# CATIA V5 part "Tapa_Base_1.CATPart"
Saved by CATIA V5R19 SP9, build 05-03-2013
Part number: Tapa_Base_1
Bounding box of the stored display mesh (mm): x -100 to 100, y -1.5 to 155, z -2.4 to 3
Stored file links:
  D:\PROGRAMACION\PROYECTOS\DEFCON\CAD\Tapa_Base_1.CATPart
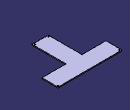
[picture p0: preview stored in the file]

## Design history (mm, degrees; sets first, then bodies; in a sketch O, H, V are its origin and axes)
Set1
  DatumCurve1 to DatumCurve21
  DatumSurface1
  DatumSurface2
  DatumCurve22 to DatumCurve29
Body1 (main body)
  Sketch1 on xy-plane, origin (0, 0, 0), H (1, 0, 0), V (0, 1, 0)
    point P1 (-25, 0)
    line L1 (-25, 0) -> (25, 0)
    line L2 (25, 0) -> (25, 105)
    line L3 (25, 105) -> (100, 105)
    line L4 (100, 105) -> (100, 155)
    line L5 (100, 155) -> (-100, 155)
    line L6 (-100, 155) -> (-100, 105)
    point P7 (-100, 105)
    line L7 (-100, 105) -> (-25, 105)
    line L8 (-25, 105) -> (-25, 0)
    length L1 = 50
    length L7 = 75
    length L2 = 105
    length L4 = 50
    coincidence: P1 H, P7 L3
    horizontal: L1 H, L3 H, L5 H, L7 H
    vertical: L2 V, L4 V, L6 V, L8 V
    symmetry: L8 L2 V, L6 L4 V
  Pad1: profile Sketch1, direction (0, 0, 1), length 3
  Sketch2 on end face of Pad1, origin (0, 0, 3), H (1, 0, 0), V (0, 1, 0)
    reference projected circle E1 centre (-96, 151) radius 2.5 from edge of DatumCurve1
    reference projected circle E3 centre (-21, 4) radius 2.5 from edge of DatumCurve3
    axis line L1 (0, 174.0259) -> (0, -25.0037)
    reference projected line E5 (-25, 105) -> (-25, 0) from edge [start face of Pad1 | face of Pad1 from Sketch1.L8]
    reference projected line E6 (25, 0) -> (25, 105) from edge [start face of Pad1 | face of Pad1 from Sketch1.L2]
    circle A1 centre (-96, 151) radius 1.7
    circle A2 centre (-21, 4) radius 1.7
    circle A3 centre (96, 151) radius 1.7
    circle A4 centre (21, 4) radius 1.7
    radius A1 = 1.7
    radius A2 = 1.7
    coincidence: L1 O
    symmetry: E5 E6 L1, A1 A3 L1, A2 A4 L1
    concentricity: A1 E1, A2 E3
  Pocket1: profile Sketch2, direction (0, 0, -1), through (limit type 6)
  Sketch3 on zx-plane, origin (0, 0, 0), H (-1, 0, 0), V (0, 0, 1)
    projected line E1 (25, 0) -> (-25, 0) from edge [start face of Pad1 | face of Pad1 from Sketch1.L1]
    projected line E2 (2.4, 0) -> (1.6, 0) from edge [start face of Pad1 | face of Pad1 from Sketch1.L1]
    projected line E3 (-1.6, 0) -> (-2.4, 0) from edge [start face of Pad1 | face of Pad1 from Sketch1.L1]
    arc A1 centre (0, 0) radius 2.4 from (-2.4, 0) to (2.4, 0) ccw
    arc A2 centre (0, 0) radius 1.6 from (-1.6, 0) to (1.6, 0) ccw
    point P3 (-2.4, 0)
    point P4 (2.4, 0)
    point P5 (-1.6, 0)
    point P6 (1.6, 0)
    radius A1 = 2.4
    radius A2 = 1.6
    coincidence: E1 P4, E1 P3, E1 P6, E1 P5
  Pad2: profile Sketch3, direction (0, 1, 0), up to face of DatumSurface1, opposite side up to face of Pad4 from Sketch6.L2
  Body2
    Sketch4 on start face of Pad1, origin (0, 0, 0), H (1, 0, 0), V (0, -1, 0)
      reference projected line E1 (23, -3) -> (-23, -3) from edge of DatumCurve5
      reference projected line E4 (-23, -49) -> (23, -49) from edge of DatumCurve8
      reference projected line E5 (23, -55) -> (-23, -55) from edge of DatumCurve9
      reference projected line E9 (98, -107) -> (-98, -107) from edge of DatumCurve13
      reference projected line E11 (-98, -153) -> (98, -153) from edge of DatumCurve15
      line L1 (-21, -3) -> (21, -3)
      line L2 (21, -3) -> (21, -49)
      line L3 (21, -49) -> (-21, -49)
      line L4 (-21, -49) -> (-21, -3)
      point P29 (-21, -55)
      line L5 (-21, -55) -> (21, -55)
      line L6 (21, -55) -> (21, -101)
      line L7 (21, -101) -> (-21, -101)
      line L8 (-21, -101) -> (-21, -55)
      point P31 (21, -101)
      construction line L9 (0, 41) -> (0, -173)
      point P33 (0, 41)
      construction line L10 (-40, -52) -> (61, -52)
      construction line L11 (-90, -113.5) -> (90, -113.5)
      construction line L12 (90, -113.5) -> (90, -146.5)
      construction line L13 (90, -146.5) -> (-90, -146.5)
      construction line L14 (-90, -146.5) -> (-90, -113.5)
      axis line L15 (-115, -130) -> (134, -130)
      length L2 = 46
      length L3 = 42
      length L6 = 46
      distance L3 E4 = 0
      distance E1 L1 = 0 (reference)
      length L13 = 180
      length L12 = 33
      horizontal: L1 H, L3 H, L5 H, L7 H, L10 H, L11 H, L13 H, L15 H
      vertical: L2 V, L4 V, L6 V, L8 V, L9 V, L12 V, L14 V
      coincidence: P29 L4, P31 L2, P33 V
      symmetry: L4 L2 L9, E4 E5 L10, L3 L5 L10, E9 E11 L15, L11 L13 L15, L14 L12 L9
    Pocket2: profile Sketch4, direction (0, 0, 1), up to face of DatumSurface2
  Remove1: tool Body2
  Body3
    Sketch5 on face of Pad1 from Sketch1.L6, origin (-100, 0, 0), H (0, -1, 0), V (0, 0, 1)
      arc A1 centre (-115, 0) radius 2.4 from (-117.4, 0) to (-112.6, 0) ccw
      point P1 (-115, 0)
      arc A2 centre (-115, 0) radius 1.6 from (-116.6, 0) to (-113.4, 0) ccw
      projected line E1 (-155, 0) -> (-105, 0) from edge [face of Pad1 | face of Pad1 from Sketch1.L6]
      projected line E2 (-117.4, 0) -> (-116.6, 0) from edge [face of Pad1 | face of Pad1 from Sketch1.L6]
      projected line E3 (-113.4, 0) -> (-112.6, 0) from edge [face of Pad1 | face of Pad1 from Sketch1.L6]
      reference projected line E4 (-105, 0) -> (-105, 3) from edge [face of Pad1 from Sketch1.L7 | face of Pad1 from Sketch1.L6]
      point P4 (-117.4, 0)
      point P5 (-112.6, 0)
      point P6 (-116.6, 0)
      point P7 (-113.4, 0)
      point P8 (-116.6, 0)
      point P9 (-113.4, 0)
      point P10 (-117.4, 0)
      point P11 (-112.6, 0)
      radius A2 = 1.6
      radius A1 = 2.4
      distance P1 E4 = 10
      coincidence: P1 E1, A1 P4, A1 P5, A2 P6, A2 P7, E1 P9, E1 P8, E1 P11, E1 P10, P4 P10, P5 P11, P6 P8, P7 P9
    Pad3: profile Sketch5, direction (1, 0, 0), length 80, opposite side length -20, deactivated
  Add1: tool Body3, deactivated
  Body4
    Sketch6 on end face of Pad1, origin (0, 0, 3), H (1, 0, 0), V (0, 1, 0)
      axis line L1 (0, 22) -> (0, -20)
      point P1 (0, 22)
      point P3 (25, 0)
      point P4 (0, -1.5)
      line L2 (0, -1.5) -> (4.4641, -1.5)
      point P5 (4.4641, -1.5)
      line L3 (4.4641, -1.5) -> (3.5981, 0)
      point P6 (3.5981, 0)
      point P7 (9.5981, 0)
      line L4 (9.5981, 0) -> (8.7321, -1.5)
      point P8 (8.7321, -1.5)
      line L5 (8.7321, -1.5) -> (14.7321, -1.5)
      point P9 (14.7321, -1.5)
      line L6 (14.7321, -1.5) -> (13.866, 0)
      point P10 (13.866, 0)
      point P11 (19.866, 0)
      line L7 (19.866, 0) -> (19, -1.5)
      point P12 (19, -1.5)
      line L8 (19, -1.5) -> (25, -1.5)
      point P13 (25, -1.5)
      reference projected point E1 (25, 0) from vertex [face of Pad1 from Sketch1.L2 | end face of Pad1 | face of Pad1 from Sketch1.L1]
      construction line L9 through (0, 0) direction (-1, 0)
      point P14 (0, -1.5)
      line L10 (25, -1.5) -> (25, 0)
      point P15 (25, 0)
      line L11 (25, 0) -> (19.866, 0)
      line L12 (13.866, 0) -> (9.5981, 0)
      line L13 (3.5981, 0) -> (0, 0)
      point P16 (0, 0)
      reference projected point E2 (25, 0) from vertex [face of Pad1 from Sketch1.L2 | end face of Pad1 | face of Pad1 from Sketch1.L1]
      point P17 (0, 0)
      construction line L14 through (0, 0) direction (-1, 0)
      construction line L15 through (0, 0) direction (0, 1)
      point P18 (-25, 0)
      point P19 (0, -1.5)
      point P20 (-4.4641, -1.5)
      point P21 (-3.5981, 0)
      point P22 (-9.5981, 0)
      point P23 (-8.7321, -1.5)
      point P24 (-14.7321, -1.5)
      point P25 (-13.866, 0)
      point P26 (-19.866, 0)
      point P27 (-19, -1.5)
      point P28 (-25, -1.5)
      point P29 (0, -1.5)
      point P30 (-25, 0)
      point P31 (0, 0)
      line L16 (0, -1.5) -> (-4.4641, -1.5)
      line L17 (-4.4641, -1.5) -> (-3.5981, 0)
      line L18 (-9.5981, 0) -> (-8.7321, -1.5)
      line L19 (-8.7321, -1.5) -> (-14.7321, -1.5)
      line L20 (-14.7321, -1.5) -> (-13.866, 0)
      line L21 (-19.866, 0) -> (-19, -1.5)
      line L22 (-19, -1.5) -> (-25, -1.5)
      line L23 (-25, -1.5) -> (-25, 0)
      line L24 (-25, 0) -> (-19.866, 0)
      line L25 (-13.866, 0) -> (-9.5981, 0)
      line L26 (-3.5981, 0) -> (0, 0)
      length L8 = 6
      length L5 = 6 {= Sketch6.length(L8)}
      angle L4 L5 = 60
      angle L3 L2 = 60
      angle L8 L7 = 60
      angle L6 L5 = 60
      distance P10 P11 = 6 {= Sketch6.length(L8)}
      distance P6 P7 = 6 {= Sketch6.length(L8)}
      length L10 = 1.5
      coincidence: P1 V, P3 H, P8 L2, P12 L5, P3 E1, P14 P4, P16 L1, L11 L9, L12 L9, L10 E2, L13 L9, P4 P19, P16 P31
      vertical: L1 V, L10 V
      horizontal: L2 H, L5 H, L8 H, L11 H, L12 H, L13 H
      symmetry: H L9 L1, P4 P14 L1, O P17 L1, H L14 L1, V L15 L1, P3 P18 L1, P4 P19 L1, P5 P20 L1, P6 P21 L1, P7 P22 L1, P8 P23 L1, P9 P24 L1, P10 P25 L1, P11 P26 L1, P12 P27 L1, P13 P28 L1, P14 P29 L1, P15 P30 L1, P16 P31 L1, L2 L16 L1, L3 L17 L1, L4 L18 L1, L5 L19 L1, L6 L20 L1, L7 L21 L1, L8 L22 L1, L10 L23 L1, L11 L24 L1, L12 L25 L1, L13 L26 L1
    Pad4: profile Sketch6, direction (0, 0, 1), up to face of Pad1
  Add2: tool Body4
  Fillet1: radius 0.3, on edge [face of Pad4 from Sketch6.L7 | face of Pad4 from Sketch6.L8]; edge [face of Pad1 from Sketch1.L1 | face of Pad4 from Sketch6.L7]; edge [face of Pad4 from Sketch6.L6 | face of Pad1 from Sketch1.L1]; edge [face of Pad4 from Sketch6.L5 | face of Pad4 from Sketch6.L6]; edge [face of Pad1 from Sketch1.L1 | face of Pad4 from Sketch6.L4]; edge [face of Pad4 from Sketch6.L4 | face of Pad4 from Sketch6.L5]; edge [face of Pad4 from Sketch6.L3 | face of Pad1 from Sketch1.L1]; edge [face of Pad2 | face of Pad4 from Sketch6.L3]; edge [face of Pad4 from Sketch6.L17 | face of Pad2]; edge [face of Pad1 from Sketch1.L1 | face of Pad4 from Sketch6.L17]; edge [face of Pad4 from Sketch6.L18 | face of Pad1 from Sketch1.L1]; edge [face of Pad4 from Sketch6.L19 | face of Pad4 from Sketch6.L18]; edge [face of Pad4 from Sketch6.L20 | face of Pad4 from Sketch6.L19]; edge [face of Pad1 from Sketch1.L1 | face of Pad4 from Sketch6.L20]; edge [face of Pad4 from Sketch6.L21 | face of Pad1 from Sketch1.L1]; edge [face of Pad4 from Sketch6.L22 | face of Pad4 from Sketch6.L21]
  Sketch7 on start face of Pad1, origin (0, 0, 0), H (1, 0, 0), V (0, -1, 0)
Body5
  Sketch8 on face of Pad1, origin (0, 0, 0), H (1, 0, 0), V (0, -1, 0)
    projected line E1 (-23, -3) -> (-23, -49) from edge of DatumCurve22
    point P1 (-23, -3)
    point P2 (-23, -49)
    projected line E2 (23, -3) -> (-23, -3) from edge of DatumCurve23
    point P3 (23, -3)
    point P4 (-23, -3)
    projected line E3 (23, -49) -> (23, -3) from edge of DatumCurve24
    point P5 (23, -49)
    point P6 (23, -3)
    projected line E4 (-23, -49) -> (23, -49) from edge of DatumCurve25
    point P7 (-23, -49)
    point P8 (23, -49)
    projected line E5 (23, -55) -> (-23, -55) from edge of DatumCurve26
    projected line E6 (-23, -55) -> (-23, -101) from edge of DatumCurve27
    projected line E7 (23, -101) -> (23, -55) from edge of DatumCurve28
    projected line E8 (-23, -101) -> (23, -101) from edge of DatumCurve29
    construction line L1 (0, 40) -> (0, -129)
    point P17 (0, 40)
    construction line L2 (-66, -52) -> (63, -52)
    axis line L3 (-62, -26) -> (72, -26)
    point P23 (-22.8, -11)
    line L4 (-22.8, -11) -> (-22, -11)
    line L5 (-22, -11) -> (-22, -41)
    line L6 (-22, -41) -> (-22.8, -41)
    line L7 (-22.8, -41) -> (-22.8, -11)
    point P24 (-22, -11)
    point P25 (-22, -41)
    point P26 (-22.8, -41)
    point P27 (-15, -3.2)
    line L8 (-15, -3.2) -> (-4, -3.2)
    line L9 (15, -3.2) -> (15, -4)
    line L10 (15, -4) -> (4, -4)
    line L11 (-15, -4) -> (-15, -3.2)
    point P28 (15, -3.2)
    point P29 (15, -4)
    point P30 (-15, -4)
    point P31 (15, -48.8)
    point P32 (-15, -48.8)
    point P33 (-15, -48)
    point P34 (15, -48)
    point P35 (22, -11)
    point P36 (22.8, -11)
    line L12 (22.8, -11) -> (22, -11)
    point P37 (22.8, -41)
    line L13 (22.8, -41) -> (22.8, -11)
    point P38 (22, -41)
    line L14 (22, -11) -> (22, -41)
    line L15 (22, -41) -> (22.8, -41)
    point P39 (0, -104)
    construction line L16 through (0, -104) direction (1, 0)
    construction line L17 through (0, -104) direction (0, -1)
    point P40 (-23, -55)
    point P41 (-23, -101)
    point P42 (-23, -101)
    point P43 (23, -101)
    point P44 (23, -101)
    point P45 (23, -55)
    point P46 (23, -55)
    point P47 (-23, -55)
    point P48 (-22.8, -93)
    point P49 (-22, -93)
    point P50 (-22, -63)
    point P51 (-22.8, -63)
    point P52 (22, -93)
    point P53 (22.8, -93)
    point P54 (22.8, -63)
    point P55 (22, -63)
    line L18 (-22.8, -93) -> (-22, -93)
    line L19 (-22, -93) -> (-22, -63)
    line L20 (-22, -63) -> (-22.8, -63)
    line L21 (-22.8, -63) -> (-22.8, -93)
    line L22 (22.8, -93) -> (22, -93)
    line L23 (22.8, -63) -> (22.8, -93)
    line L24 (22, -93) -> (22, -63)
    line L25 (22, -63) -> (22.8, -63)
    construction line L26 (-23, -101) -> (-23, -55)
    construction line L27 (23, -101) -> (-23, -101)
    construction line L28 (23, -55) -> (23, -101)
    construction line L29 (-23, -55) -> (23, -55)
    line L30 (-4, -3.2) -> (-4, -4)
    point P56 (-4, -3.2)
    point P57 (-4, -4)
    line L31 (4, -3.2) -> (4, -4)
    point P58 (4, -3.2)
    point P59 (4, -4)
    line L32 (4, -3.2) -> (15, -3.2)
    line L33 (-4, -4) -> (-15, -4)
    point P60 (-15, -48.8)
    point P61 (-15, -48)
    line L34 (-15, -48) -> (-15, -48.8)
    point P62 (-4, -48.8)
    line L35 (-15, -48.8) -> (-4, -48.8)
    point P63 (-4, -48)
    line L36 (-4, -48) -> (-15, -48)
    line L37 (-4, -48.8) -> (-4, -48)
    point P64 (4, -48)
    point P65 (4, -48.8)
    line L38 (4, -48.8) -> (4, -48)
    point P66 (15, -48.8)
    line L39 (4, -48.8) -> (15, -48.8)
    point P67 (15, -48)
    line L40 (15, -48) -> (4, -48)
    line L41 (15, -48.8) -> (15, -48)
    point P68 (0, -104)
    construction line L42 through (0, -104) direction (1, 0)
    point P69 (-15, -100.8)
    point P70 (15, -100.8)
    point P71 (15, -100)
    point P72 (-15, -100)
    point P73 (15, -55.2)
    point P74 (-15, -55.2)
    point P75 (-15, -56)
    point P76 (15, -56)
    point P77 (-4, -100.8)
    point P78 (-4, -100)
    point P79 (4, -100.8)
    point P80 (4, -100)
    point P81 (-15, -55.2)
    point P82 (-15, -56)
    point P83 (-4, -55.2)
    point P84 (-4, -56)
    point P85 (4, -56)
    point P86 (4, -55.2)
    point P87 (15, -55.2)
    point P88 (15, -56)
    line L43 (-15, -100.8) -> (-4, -100.8)
    line L44 (15, -100.8) -> (15, -100)
    line L45 (15, -100) -> (4, -100)
    line L46 (-15, -100) -> (-15, -100.8)
    line L47 (-4, -100.8) -> (-4, -100)
    line L48 (4, -100.8) -> (4, -100)
    line L49 (4, -100.8) -> (15, -100.8)
    line L50 (-4, -100) -> (-15, -100)
    line L51 (-15, -56) -> (-15, -55.2)
    line L52 (-15, -55.2) -> (-4, -55.2)
    line L53 (-4, -56) -> (-15, -56)
    line L54 (-4, -55.2) -> (-4, -56)
    line L55 (4, -55.2) -> (4, -56)
    line L56 (4, -55.2) -> (15, -55.2)
    line L57 (15, -56) -> (4, -56)
    line L58 (15, -55.2) -> (15, -56)
    length L5 = 30
    distance L7 E1 = 0.2
    length L6 = 0.8
    distance L8 E2 = 0.2
    length L9 = 0.8
    distance P29 P30 = 30
    distance L30 L31 = 8
    length L33 = 11 (reference)
    coincidence: P17 V, P57 L10, P58 L8, L8 L32, L10 L33
    vertical: L1 V, L5 V, L7 V, L9 V, L11 V, L30 V, L31 V
    horizontal: L2 H, L3 H, L4 H, L6 H, L8 H, L10 H, L32 H, L33 H
    symmetry: E4 E5 L2, E1 E3 L1, E2 E4 L3, L4 L6 L3, L11 L9 L1, P28 P31 L3, P27 P32 L3, P30 P33 L3, P29 P34 L3, P24 P35 L1, P23 P36 L1, L4 L12 L1, P26 P37 L1, L7 L13 L1, P25 P38 L1, L5 L14 L1, L6 L15 L1, O P39 L2, H L16 L2, V L17 L2, P2 P40 L2, P1 P41 L2, E1 L26 L2, P4 P42 L2, P3 P43 L2, E2 L27 L2, P6 P44 L2, P5 P45 L2, E3 L28 L2, P8 P46 L2, P7 P47 L2, E4 L29 L2, P23 P48 L2, P24 P49 L2, P25 P50 L2, P26 P51 L2, P35 P52 L2, P36 P53 L2, P37 P54 L2, P38 P55 L2, L4 L18 L2, L5 L19 L2, L6 L20 L2, L7 L21 L2, L12 L22 L2, L13 L23 L2, L14 L24 L2, L15 L25 L2, L30 L31 L17, P27 P60 L3, P30 P61 L3, L11 L34 L3, P56 P62 L3, L8 L35 L3, P57 P63 L3, L33 L36 L3, L30 L37 L3, P59 P64 L3, P58 P65 L3, L31 L38 L3, P28 P66 L3, L32 L39 L3, P29 P67 L3, L10 L40 L3, L9 L41 L3, O P68 L2, H L42 L2, P27 P69 L2, P28 P70 L2, P29 P71 L2, P30 P72 L2, P31 P73 L2, P32 P74 L2, P33 P75 L2, P34 P76 L2, P56 P77 L2, P57 P78 L2, P58 P79 L2, P59 P80 L2, P60 P81 L2, P61 P82 L2, P62 P83 L2, P63 P84 L2, P64 P85 L2, P65 P86 L2, P66 P87 L2, P67 P88 L2, L8 L43 L2, L9 L44 L2, L10 L45 L2, L11 L46 L2, L30 L47 L2, L31 L48 L2, L32 L49 L2, L33 L50 L2, L34 L51 L2, L35 L52 L2, L36 L53 L2, L37 L54 L2, L38 L55 L2, L39 L56 L2, L40 L57 L2, L41 L58 L2
  Pad5: profile Sketch8, direction (0, 0, -1), length 1.5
